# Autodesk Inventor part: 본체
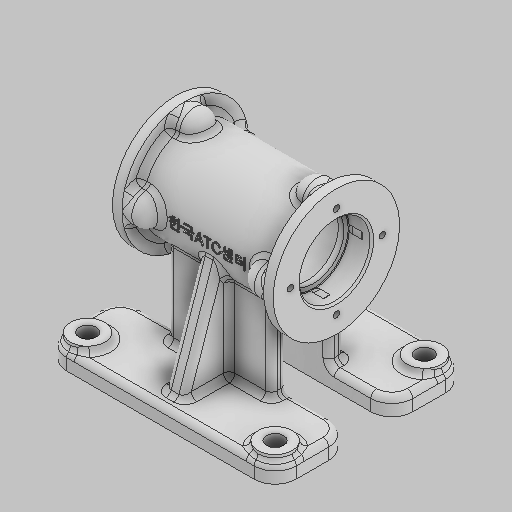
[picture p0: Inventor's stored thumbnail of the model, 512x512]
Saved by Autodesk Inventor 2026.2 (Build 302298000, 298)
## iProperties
Created: 2026-06
Part Number: 본체
Material: 일반
Document SubType Name: Modeling
Designer: sec7
Density: 1 g/cm^3
Appearance: 기본값
Author: sec7
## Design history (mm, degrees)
sketch "스케치1"
  geometry: L1 (-42, 0)-(42, 0); L2 (-42, 0)-(-42, 33); L3 (-42, 33)-(-37, 33); L4 (-37, 33)-(-37, 25); L5 (-37, 25)-(37, 25); L6 (37, 25)-(37, 33); L7 (37, 33)-(42, 33); L8 (42, 33)-(42, 0); L9 (-42, 18.5)-(-30.3, 18.5); L10 (-30, 18.2)-(-30, 0); L11 (42, 18.5)-(30.3, 18.5); L12 (30, 18.2)-(30, 0); L13 (-27, 0)-(-27, 20); L14 (-27, 20)-(27, 20); L15 (27, 20)-(27, 0); L16 (-30, 16)-(-27, 16); L17 (27, 16)-(30, 16); L18 (-37, 31.811)-(-32, 31.811); L19 (-37, 25)-(-24.089, 25); L20 (-37, 31.811)-(-37, 25); A1 r 0.3 centre (-30.3, 18.2) between (-30, 18.2) and (-30.3, 18.5); A2 r 0.3 centre (30.3, 18.2) between (30.3, 18.5) and (30, 18.2); A3 r 8 centre (-32, 23.811) between (-24.089, 25) and (-32, 31.811); 6 further points
  constraints: 40 end point, 18 point on line, 11 perpendicular, 6 point on circle, 5 tangent, 4 horizontal, 3 centre point, 3 midpoint, 2 collinear, 2 vertical, 1 coincident, 1 equal radius, 1 vertical alignment
  dimensions: "d0" = 84 distance of L1.start L1.end; "d1" = 66 diameter of L3 L1; "d2" = 50 diameter of L5 L1; "d3" = 5 distance between parallel lines of L2 L4; "d4" = 5 distance between parallel lines of L6 L8; "d5" = 12 distance between parallel lines of L10 L2; "d6" = 12 distance between parallel lines of L12 L8; "d7" = 40 diameter of L14 L1; "d8" = 66 diameter of L7 L1; "d9" = 37 diameter of L9 L1; "d10" = 37 diameter of L11 L1; "d11" = 32 diameter of L17 L1; "d12" = 54 distance of L13.end L14.end; "d14" = 0.3 radius of A1; "d123" = 8 radius of A3; "d124" = 10 distance from line of L18.end L2; "d129" = 1.1894 distance between parallel lines of L7 L18
revolve "회전1" stored, may be unused: angle "d13" = 360 deg
node "작업 평면4"
sketch "스케치2"
  geometry: L1 (60, 50)-(-60, 50); L2 (-60, 50)-(-60, 11); L3 (-60, 11)-(60, 11); L4 (60, 11)-(60, 50); L5 (60, -11)-(-60, -11); L6 (-60, -11)-(-60, -50); L7 (-60, -50)-(60, -50); L8 (60, -50)-(60, -11); 3 further points
  constraints: 16 end point, 4 parallel, 2 horizontal, 2 midpoint, 2 perpendicular, 2 point on line, 1 vertical alignment
  dimensions: "d18" = 39 distance of L7.end L5.start; "d19" = 39 distance of L3.end L1.start; "d21" = 50 distance from line of L1 point (0, 0); "d22" = 50 distance from line of L7 point (0, 0); "d23" = 60 distance from line of L8 point (0, -50)
extrude "돌출1" join sketch "스케치2" distance "d24" = 9; taper "d25" = 0 deg
sketch "스케치3"
  geometry: L1 (60, -11)-(-60, -11) reference; L2 (-27, -11)-(27, -11); L3 (27, -11)-(27, -19); L4 (27, -19)-(-27, -19); L5 (-27, -19)-(-27, -11); 4 further points
  constraints: 8 end point, 2 midpoint, 2 parallel, 1 horizontal, 1 perpendicular, 1 point on line, 1 vertical alignment
  dimensions: "d26" = 54 distance of L3.end L4.end; "d27" = 8 distance between parallel lines of L4 L1
extrude "돌출2" join sketch "스케치3" stored distance "d28" = 9; taper "d29" = 0 deg
sketch "스케치4"
  geometry: L1 (-60, 11)-(60, 11) reference; L2 (-27, 11)-(27, 11); L3 (27, 11)-(27, 19); L4 (27, 19)-(-27, 19); L5 (-27, 19)-(-27, 11); 4 further points
  constraints: 8 end point, 2 midpoint, 2 parallel, 1 horizontal, 1 perpendicular, 1 point on line, 1 vertical alignment
  dimensions: "d30" = 54 distance of L3.end L4.end; "d31" = 8 distance of L2.end L3.end
extrude "돌출3" join sketch "스케치4" stored distance "d32" = 10; taper "d33" = 0 deg
node "작업 평면5"
sketch "스케치5"
  geometry: L1 (-6.346, 24.181)-(-61, 43); L2 (-61, 11)-(-61, 50) reference; L3 (-70, 50)-(-61, 50) reference; L4 (-61, 19)-(-16.248, 19) reference; L5 (-6.346, -24.181)-(-61, -43); L6 (-61, -50)-(-61, -11) reference; L7 (-70, -50)-(-61, -50) reference; L8 (-61, -19)-(-16.248, -19) reference; A1 r 25 centre (0, 0) between (-6.346, 24.181) and (-16.248, 19) reference; 1 further point
  constraints: 4 end point, 2 point on circle, 2 point on line
  dimensions: "d36" = 7 distance from line of L1.end L3; "d37" = 19 deg angle of L4 L1; "d38" = 7 distance from line of L5.end L7; "d39" = 19 deg angle of L8 L5
extrude "돌출4" join sketch "스케치5" stored distance "d40" = 10; taper "d41" = 0 deg
sketch "스케치6"
  geometry: A1 r 24 centre (0, 0) between (0, 24) and (-24, 0); 3 further points
  constraints: 4 point on circle, 1 centre point, 1 coincident
  dimensions: "d42" = 48 diameter of A1
hole "구멍1" sketch "스케치6" at (0, 24), (-24, 0), (0, -24), (24, 0) diameter "d43" = 3.242; stored, may be unused: countersink angle "d47" = 90 deg, drill point angle "d49" = 118 deg; dims "d44" = 8, "d45" = 4, "d46" = 2, "d48" = 10
sketch "스케치8"
  geometry: L1 (0, 0)-(0, 25); C1 r 18.5 at (0, 0) reference; C2 r 8 at (0, 25); C3 r 33 at (0, 0) reference; C4 r 8 at (-25, 0); C5 r 8 at (0, -25); C6 r 8 at (25, 0); C7 r 25 at (0, 0); 17 further points
  constraints: 5 centre point, 2 coincident, 2 end point, 1 tangent, 1 vertical, 9 other
  dimensions: "d64" = 8 radius of C2; "d74" = 360 deg dimension on point (0, 0) C2.centre (derived); "d112" = 50 diameter of C7
  node "스케치 - 원형 패턴3" dims "d74" = 360 deg (derived)
node "작업 평면9"
sketch "스케치10"
  geometry: L1 (42, 33)-(42, -33) reference; L2 (-60, -50)-(60, -50) reference; L3 (60, 50)-(-60, 50) reference; C1 r 9 at (49, 39); C2 r 9 at (49, -39); 4 further points
  constraints: 3 midpoint, 2 centre point
  dimensions: "d84" = 18 diameter of C1; "d85" = 39 vertical distance of C1.centre point (42, 0); "d86" = 18 diameter of C2; "d87" = 39 vertical distance of C2.centre point (42, 0); "d88" = 49 horizontal distance of point (0, -50) C2.centre; "d89" = 49 horizontal distance of point (0, 50) C1.centre (= d88)
extrude "돌출7" join sketch "스케치10" distance "d90" = 3; taper "d91" = 0 deg
sketch "스케치11"
  geometry: C1 r 9 at (0, 0) reference; 2 further points
  constraints: 1 coincident
hole "구멍3" sketch "스케치11" at (0, 0) diameter "d92" = 9; stored, may be unused: countersink angle "d96" = 90 deg, drill point angle "d98" = 0 deg; dims "d93" = 6, "d94" = 4, "d95" = 2, "d97" = 12
sketch "스케치12"
  geometry: C1 r 9 at (0, 0) reference; 2 further points
  constraints: 1 coincident
hole "구멍4" sketch "스케치12" at (0, 0) diameter "d99" = 9; stored, may be unused: countersink angle "d103" = 90 deg, drill point angle "d105" = 0 deg; dims "d100" = 6, "d101" = 4, "d102" = 2, "d104" = 12
chamfer "모따기1" distance "d106" = 1; stored, may be unused: second distance "d107" = 2, angle "d108" = 45 deg
chamfer "모따기2" distance "d109" = 1; stored, may be unused: second distance "d110" = 2, angle "d111" = 45 deg
extrude "돌출8" join sketch "스케치8" distance "d113" = 13; taper "d114" = 0 deg
node "작업 평면10"
sketch "스케치13"
  geometry: L1 (-10.365, 3.002)-(10.365, 3.002); L2 (10.365, 3.002)-(10.365, -3.002); L3 (10.365, -3.002)-(-10.365, -3.002); L4 (-10.365, -3.002)-(-10.365, 3.002); L5 (-60, -70)-(60, -70) reference; 4 further points
  constraints: 3 midpoint, 1 vertical alignment, 2 other
  dimensions: "d120" = 70 distance from line of L5 point (10.365, 0)
feature "엠보싱1" sketch "스케치13" dims "d121" = 0.5, "d122" = 0
revolve "회전3" stored, may be unused: angle "d125" = 90 deg
fillet "모깎기5" dims "d130" = 11
node "작업 평면12"
sketch "스케치15"
  geometry: L1 (-27, -19)-(-27, -11) reference; L2 (-49, 11)-(49, 11) reference; L3 (49, -11)-(-49, -11) reference; L4 (-27, 11)-(26.915, 11); L5 (26.915, -11)-(-27, -11); L6 (-5, 11)-(-5, -11); L7 (5, 11)-(5, -11); 5 further points
  constraints: 8 end point, 7 point on line, 2 collinear, 2 perpendicular
  dimensions: "d137" = 5 distance from line of L6 point (0, 0); "d138" = 5 distance from line of point (0, 0) L7
extrude "돌출9" join sketch "스케치15" stored distance "d135" = 13; taper "d136" = 0 deg
fillet "모깎기11" dims "d144" = 3, "d145" = 3
fillet "모깎기12" dims "d146" = 3
fillet "모깎기13" dims "d147" = 3
fillet "모깎기14" dims "d148" = 3
fillet "모깎기15" dims "d149" = 3
fillet "모깎기16" dims "d150" = 8
fillet "모깎기17" dims "d151" = 3
fillet "모깎기18" dims "d152" = 3
fillet "모깎기6" dims "d139" = 3
fillet "모깎기7" dims "d140" = 3
fillet "모깎기8" dims "d141" = 3
fillet "모깎기9" dims "d142" = 3
node "솔리드1"
mirror "미러1"
mirror "미러4"
mirror "미러5"
pattern_circular "원형 패턴1" dims angle "d127" = 360 deg
mirror "미러6"
feature "A9D066F2-1C7D-4E18-AEED-F7BC21143FA4" dims "d92" = 9, "d93" = 6, "d94" = 4, "d95" = 2, "d96" = 90 deg, "d97" = 12, "d98" = 0
other parameters: "d35" = 0, "d83" = -61, "d119" = 38.25
